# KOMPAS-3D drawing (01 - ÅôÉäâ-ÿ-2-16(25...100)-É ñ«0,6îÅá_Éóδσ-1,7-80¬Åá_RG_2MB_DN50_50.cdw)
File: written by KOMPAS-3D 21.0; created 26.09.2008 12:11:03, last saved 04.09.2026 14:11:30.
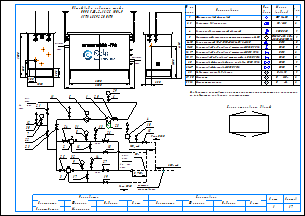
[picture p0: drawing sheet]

Sheets 1-2: A3, landscape

Document properties: Наименование: Макро:21; Автор: RaskoAdmin; Форматы листов документа: 2xA3; Полное имя файла: \\ur38nt01\Departments\КТО\КБ ПУРДГ\Заявки\Прайс-лист на типовые шкафы ГРПШ\ПУРДГ_стандарт_30_04_2026\ПУРДГ с RG_2MB\ПУРДГ-Ш-2-16(25...100)-Р до0,6МПа_Рвых-1,7-80кПа_RG_2MB_DN50_50.cdw

Title block, sheet 1: Наименование: Пункт учета газа / ПУГ-Ш-400-Р / ЛГТИ.485922.001ТУ; designation: ЛГТИ.03.4411141; sheet number: 1; Количество листов документа: 2; organisation: ООО "ЭЛЬСТЕР Газэлектроника"; Форматы листов документа: A3; stored path: C:\Рабочие документы\Компас\ПУГ\Схема.cdw; Разработал: Устинов; Проверил: Кошкин; Утвердил: Кошкин
Title block, sheet 2: sheet number: 2; stored path: D:\Рабочие документы\Заявки\ПУРДГ\ПУРДГ-ШУЭО-2-100-Р 4411220.cdw; designation, second copy: ЛГТИ.03.4411141-

Views: Вид 1, Вид 2
Referenced files: wcvoit.frw
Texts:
  Normal
  № на
  схеме
  Усл.
  обозн.
  Марка
  (модель)
  Кол.
  Фильтр газовый фланцевый
  ФГ 16-50
  Регулятор давления газа
  RG/2MB
  Клапан предохранительный сбросной
  КПС DN20
  Измерительный комплекс с ротационным счетчиком Ду50
  СГ-ЭК-Р-(0,2...2,0)-
  Кран кнопочный VE-РАСКО-НЗ-1,6-G1/2-М20
  DN15
  Кран шаровой "под приварку" штуцерный DN20 PN16
  DN20
  Кран шаровой "под приварку" штуцерный DN15 PN16
  Кран шаровой "под приварку" штуцерный п/п DN20 PN16
  Кран шаровой фланцевый с мех. приводом DN50 PN16
  Кран шаровой фланцевый DN50 PN16
  DN50
  Индикатор перепада давления
  Манометр
  Манометр-напоромер
  Delta 15
  0...     МПа
  0...     кПа
  Общий вид и габариты шкафа
  ПУРДГ-Ш-2-16(25...100)-Р
  Выход газа
  Вход газа
  logo-rasko-ge.png
  DN 1
  местное
  сопротивление
  Римп DN20
  Выход
  газа
  Р=     кПа
  Вход
  Р=       МПа
  PDI
  Схема открывания дверей
  Предприятие изготовитель может заменять комплектующие на аналогичные,
  не ухудшающие заявленных характеристик.
  Должность
  Конструктор
  Фамилия
  Подпись
  Дата
  Согласовано
  Максимкин
  Лист
  Листов
  POLYLINE_STYLE_0.18_RGB_0_0_0
  POLYLINE_STYLE_0.50_RGB_0_0_0
  POLYLINE_STYLE_0.34_RGB_0_0_0
  PHANTOM_RGB_0_0_0_SC_1_THICK_0.18
  K5LT_THIN_RGB_0_0_0_THICK_0.18
  K5LT32769_RGB_0_0_0_THICK_0.18
  K5LT12_RGB_0_0_0_SC_1_THICK_0.18
  K5LT_DASHED_RGB_0_0_0_SC_1_THICK_0.18
  ACISOTGL_RGB_0_0_0_SC_0.8_THICK_0.25
  CONTINUOUS_RGB_0_127_31_THICK_0.3
  CONTINUOUS_RGB_0_0_255_THICK_0.35
  CONTINUOUS_RGB_255_0_0_THICK_0.35
  POLYLINE_STYLE_0.25_RGB_0_0_0
  CONTINUOUS_RGB_0_0_0_THICK_0.5
  POLYLINE_STYLE_0.35_RGB_0_0_255
  CONTINUOUS_RGB_0_0_0_THICK_0.4
  CONTINUOUS_RGB_0_0_0_THICK_0.35
  НЕВИДИМАЯ_RGB_0_0_0_SC_0.3_THICK_0.25
  СONTINUOUS_RGB_0_0_0_THICK_0.25
  ОСЕВАЯ2_RGB_248_153_30_SC_0.3_THICK_0.25
  Без оформления
Dimensions and other numbers on the sheet: 1; 2, 3; 2; 4; 5; 6-10; 11-15; 16, 17; 18, 19; 20; 21-27; 7; 28; 29, 30; 31, 32; 1500; 250; 300; 1050; 550; 305; 2000; 4130; 2300; 5,,,7DN 1; 30; 12; 21; 22; 23; 11; 6; 29; 24; 31; 8; 16; 13; 26; 18; 10; 15; 25; 32; 9; 3; 17; 14; 27; 19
